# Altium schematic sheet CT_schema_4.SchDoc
size 591 x 347 mm
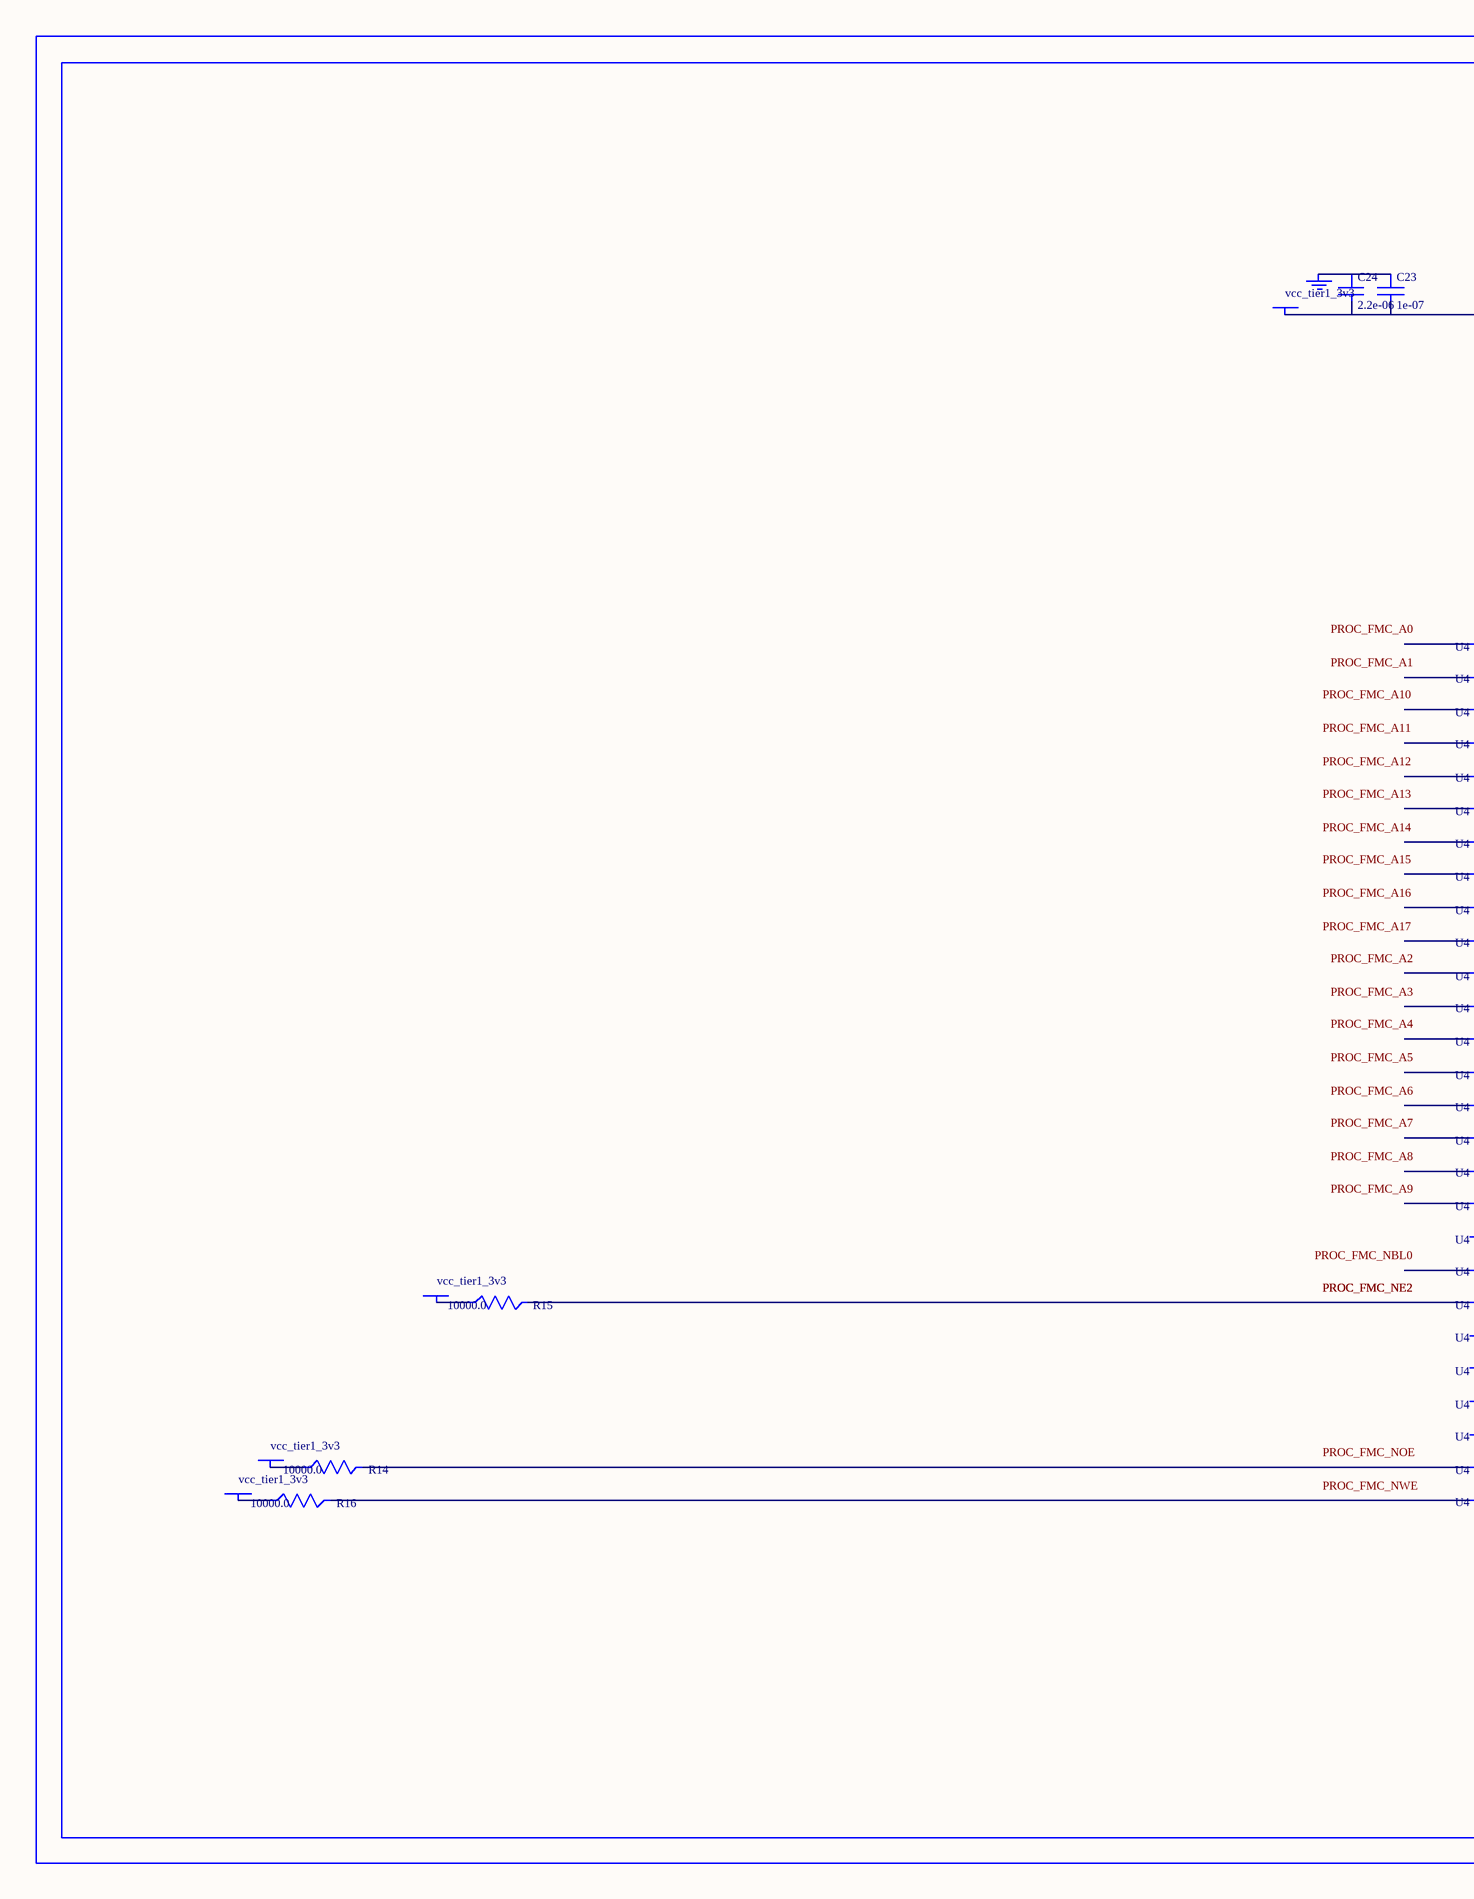
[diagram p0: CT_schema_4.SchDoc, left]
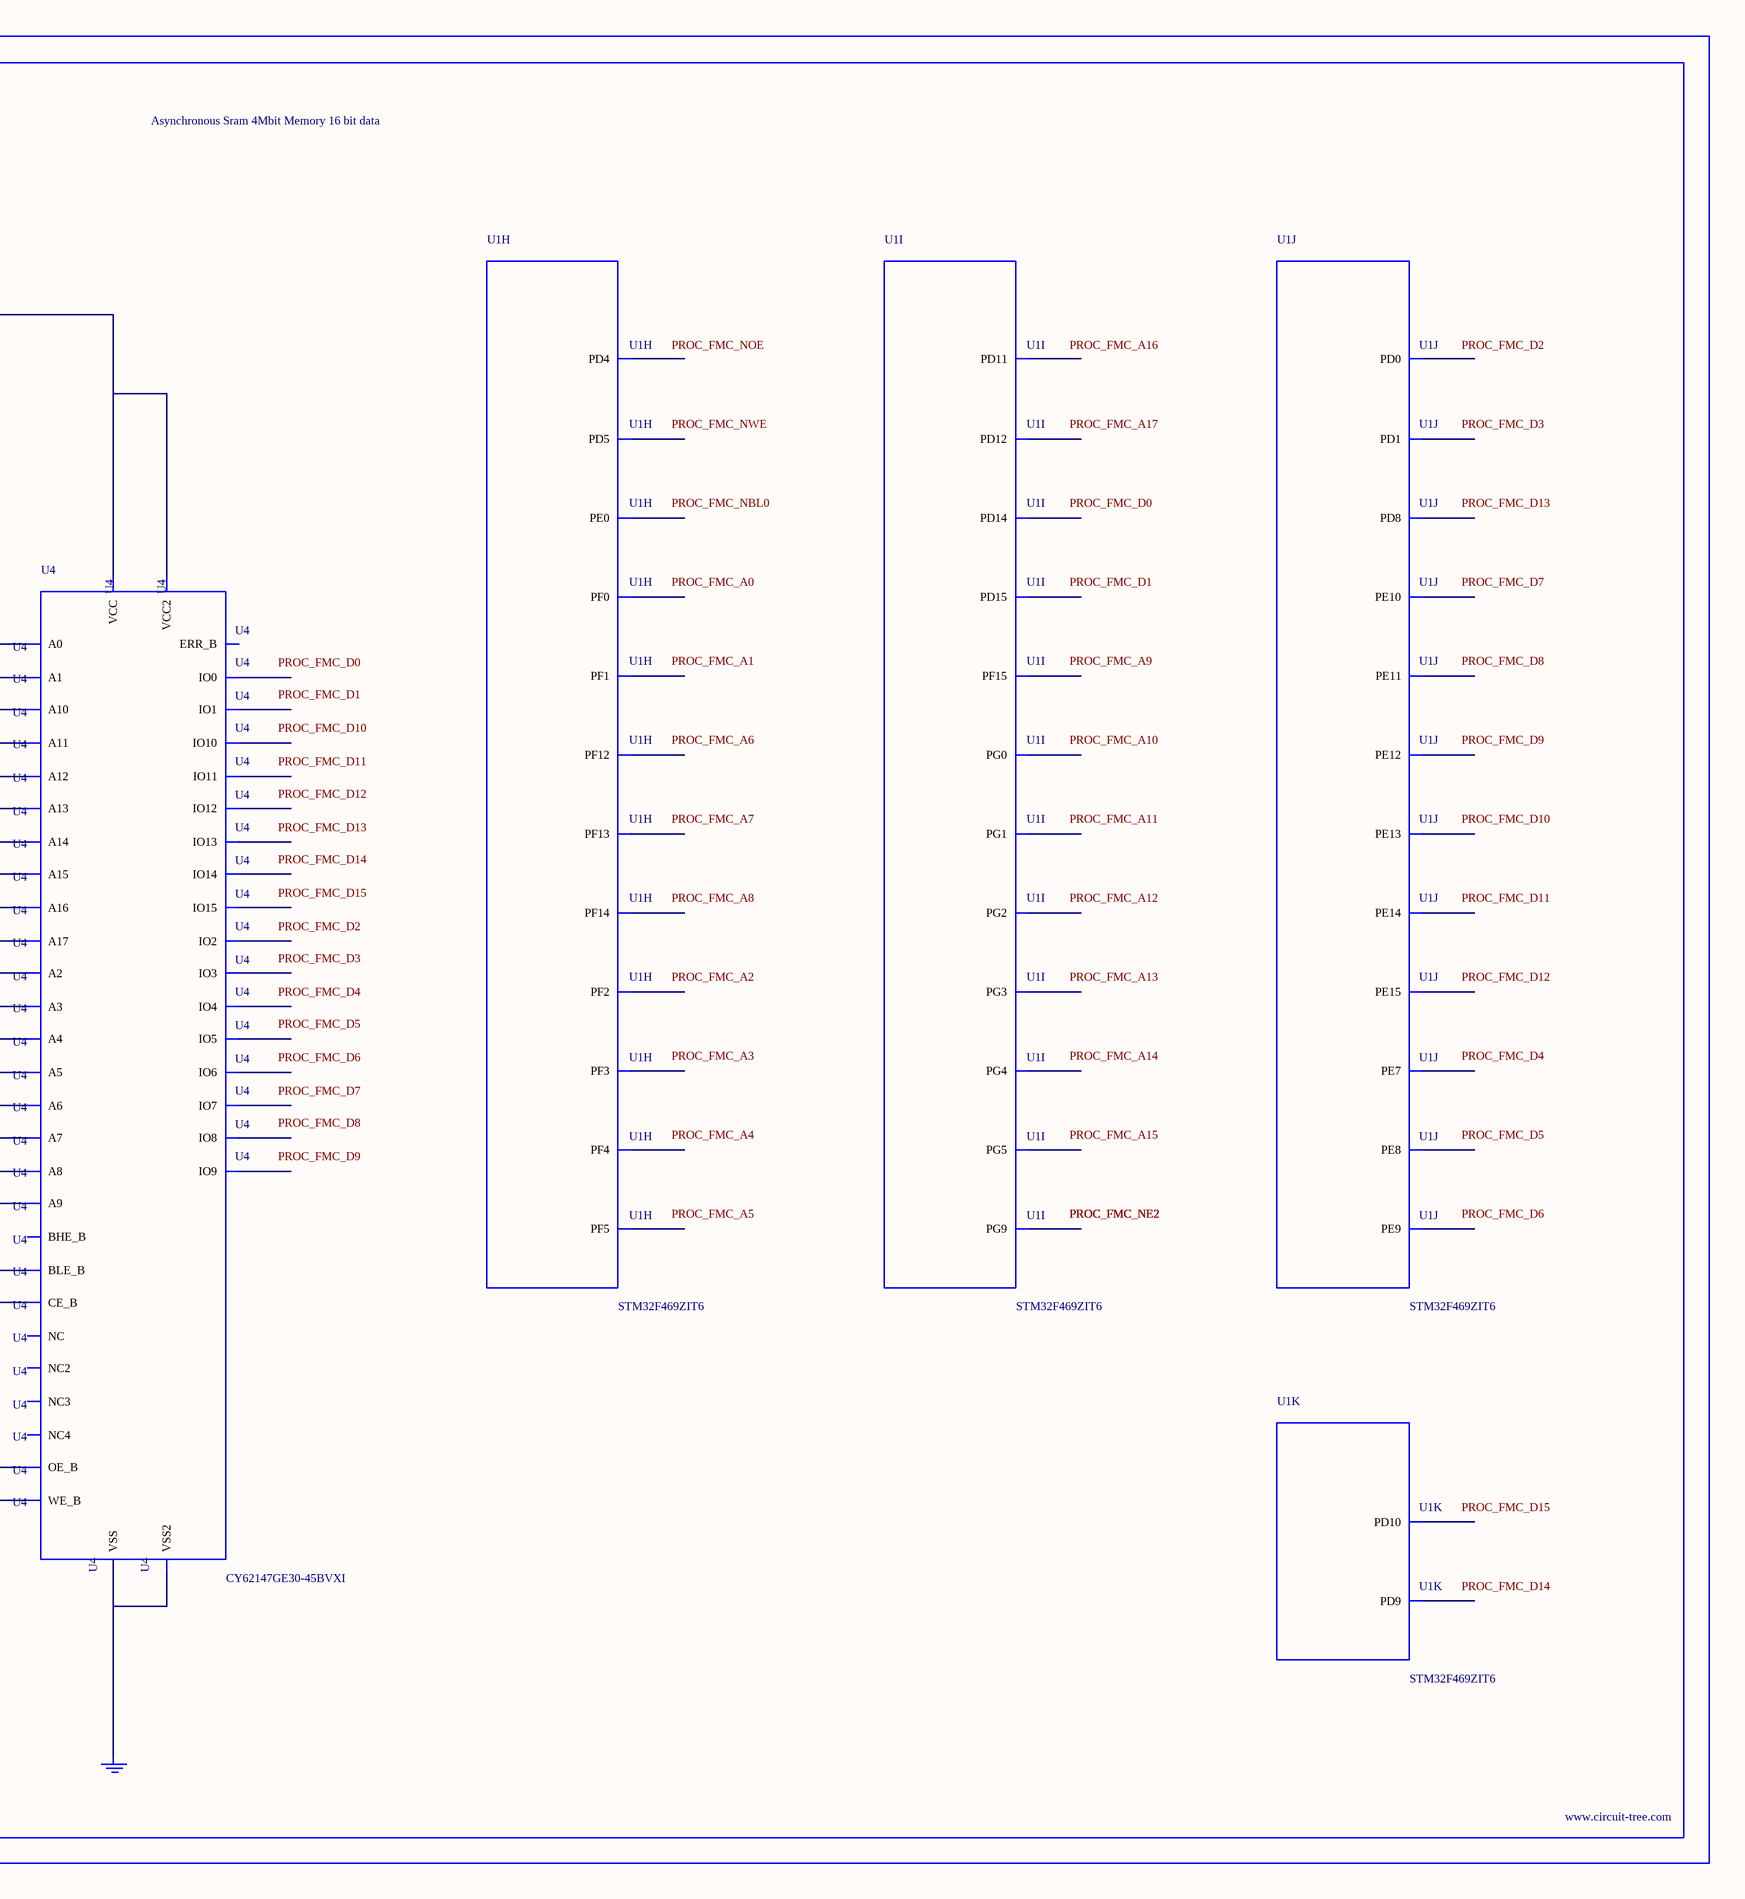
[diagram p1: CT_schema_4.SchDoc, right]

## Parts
BORDER3  (no value)
C23  1e-07  [C0402]
C24  2.2e-06  [C0603]
GND_INSTANCE_3_0  (no value)
GND_INSTANCE_3_1  (no value)
POWER_INSTANCE_3_0  vcc_tier1_3v3
POWER_INSTANCE_3_1  vcc_tier1_3v3
POWER_INSTANCE_3_2  vcc_tier1_3v3
POWER_INSTANCE_3_3  vcc_tier1_3v3
R14  10000.0  [R0603]
R15  10000.0  [R0603]
R16  10000.0  [R0603]
U1  STM32F469ZIT6  [LQFP144]  (parts H,I,J,K of 14)
U4  CY62147GE30-45BVXI  [VFBGA48]

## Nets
NetC23_1: C23.1 C24.1 GND_INSTANCE_3_0.0(GND)
NetC23_2: C23.2 C24.2 POWER_INSTANCE_3_0.0(PWR) U4.D6(VCC) U4.E1(VCC2)
NetGND_INSTANCE_3_1_0: GND_INSTANCE_3_1.0(GND) U4.D1(VSS) U4.E6(VSS2)
NetPOWER_INSTANCE_3_1_0: POWER_INSTANCE_3_1.0(PWR) R14.1
NetPOWER_INSTANCE_3_2_0: POWER_INSTANCE_3_2.0(PWR) R15.1
NetPOWER_INSTANCE_3_3_0: POWER_INSTANCE_3_3.0(PWR) R16.1
NetR14_2: R14.2 U4.A2(OE_B)
NetR15_2: R15.2 U4.B5(CE_B)
NetR16_2: R16.2 U4.G5(WE_B)

Not connected (* = marked no-connect by the designer): U1 9(PF0) 10(PF1) 11(PF2) 12(PF3) 13(PF4) 14(PF5) 45(PF12) 47(PF13) 48(PF14) 49(PF15) 50(PG0) 51(PG1) 52(PE7) 53(PE8) 54(PE9) 57(PE10) 58(PE11) 59(PE12) 60(PE13) 61(PE14) 62(PE15) 71(PD8) 72(PD9) 73(PD10) 74(PD11) 75(PD12) 78(PD14) 79(PD15) 90(PG2) 91(PG3) 92(PG4) 93(PG5) 116(PD0) 117(PD1) 120(PD4) 121(PD5) 125(PG9) 140(PE0); U4 A1(BLE_B) A3(A0) A4(A1) A5(A2) A6(NC) B1(IO8) B2(BHE_B) B3(A3) B4(A4) B6(IO0) C1(IO9) C2(IO10) C3(A5) C4(A6) C5(IO1) C6(IO2) D2(IO11) D3(A17) D4(A7) D5(IO3) E2(IO12) E3(ERR_B) E4(A16) E5(IO4) F1(IO14) F2(IO13) F3(A14) F4(A15) F5(IO5) F6(IO6) G1(IO15) G2(NC2) G3(A12) G4(A13) G6(IO7) H1(NC3) H2(A8) H3(A9) H4(A10) H5(A11) H6(NC4)

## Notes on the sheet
- Labels drawn without touching a wire or pin: PROC_FMC_A0, PROC_FMC_A1, PROC_FMC_A2, PROC_FMC_A3, PROC_FMC_A4, PROC_FMC_A5, PROC_FMC_A6, PROC_FMC_A7, PROC_FMC_A8, PROC_FMC_A9, PROC_FMC_A10, PROC_FMC_A11, PROC_FMC_A12, PROC_FMC_A13, PROC_FMC_A14, PROC_FMC_A15, PROC_FMC_A16, PROC_FMC_A17, PROC_FMC_D0, PROC_FMC_D1, PROC_FMC_D2, PROC_FMC_D3, PROC_FMC_D4, PROC_FMC_D5, PROC_FMC_D6, PROC_FMC_D7, PROC_FMC_D8, PROC_FMC_D9, PROC_FMC_D10, PROC_FMC_D11, PROC_FMC_D12, PROC_FMC_D13, PROC_FMC_D14, PROC_FMC_D15, PROC_FMC_NBL0, PROC_FMC_NOE, PROC_FMC_NWE

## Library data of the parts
BORDER3 = BORDER_PAGE3
C23 = C0402C104K3RACTU
C24 = C0603C225K8RACTU
GND_INSTANCE_3_0 GND_INSTANCE_3_1 = GND
POWER_INSTANCE_3_0-POWER_INSTANCE_3_3 = PWR
R14-R16 = RC0603JR-0710KL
